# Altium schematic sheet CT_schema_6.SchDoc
size 269 x 267 mm
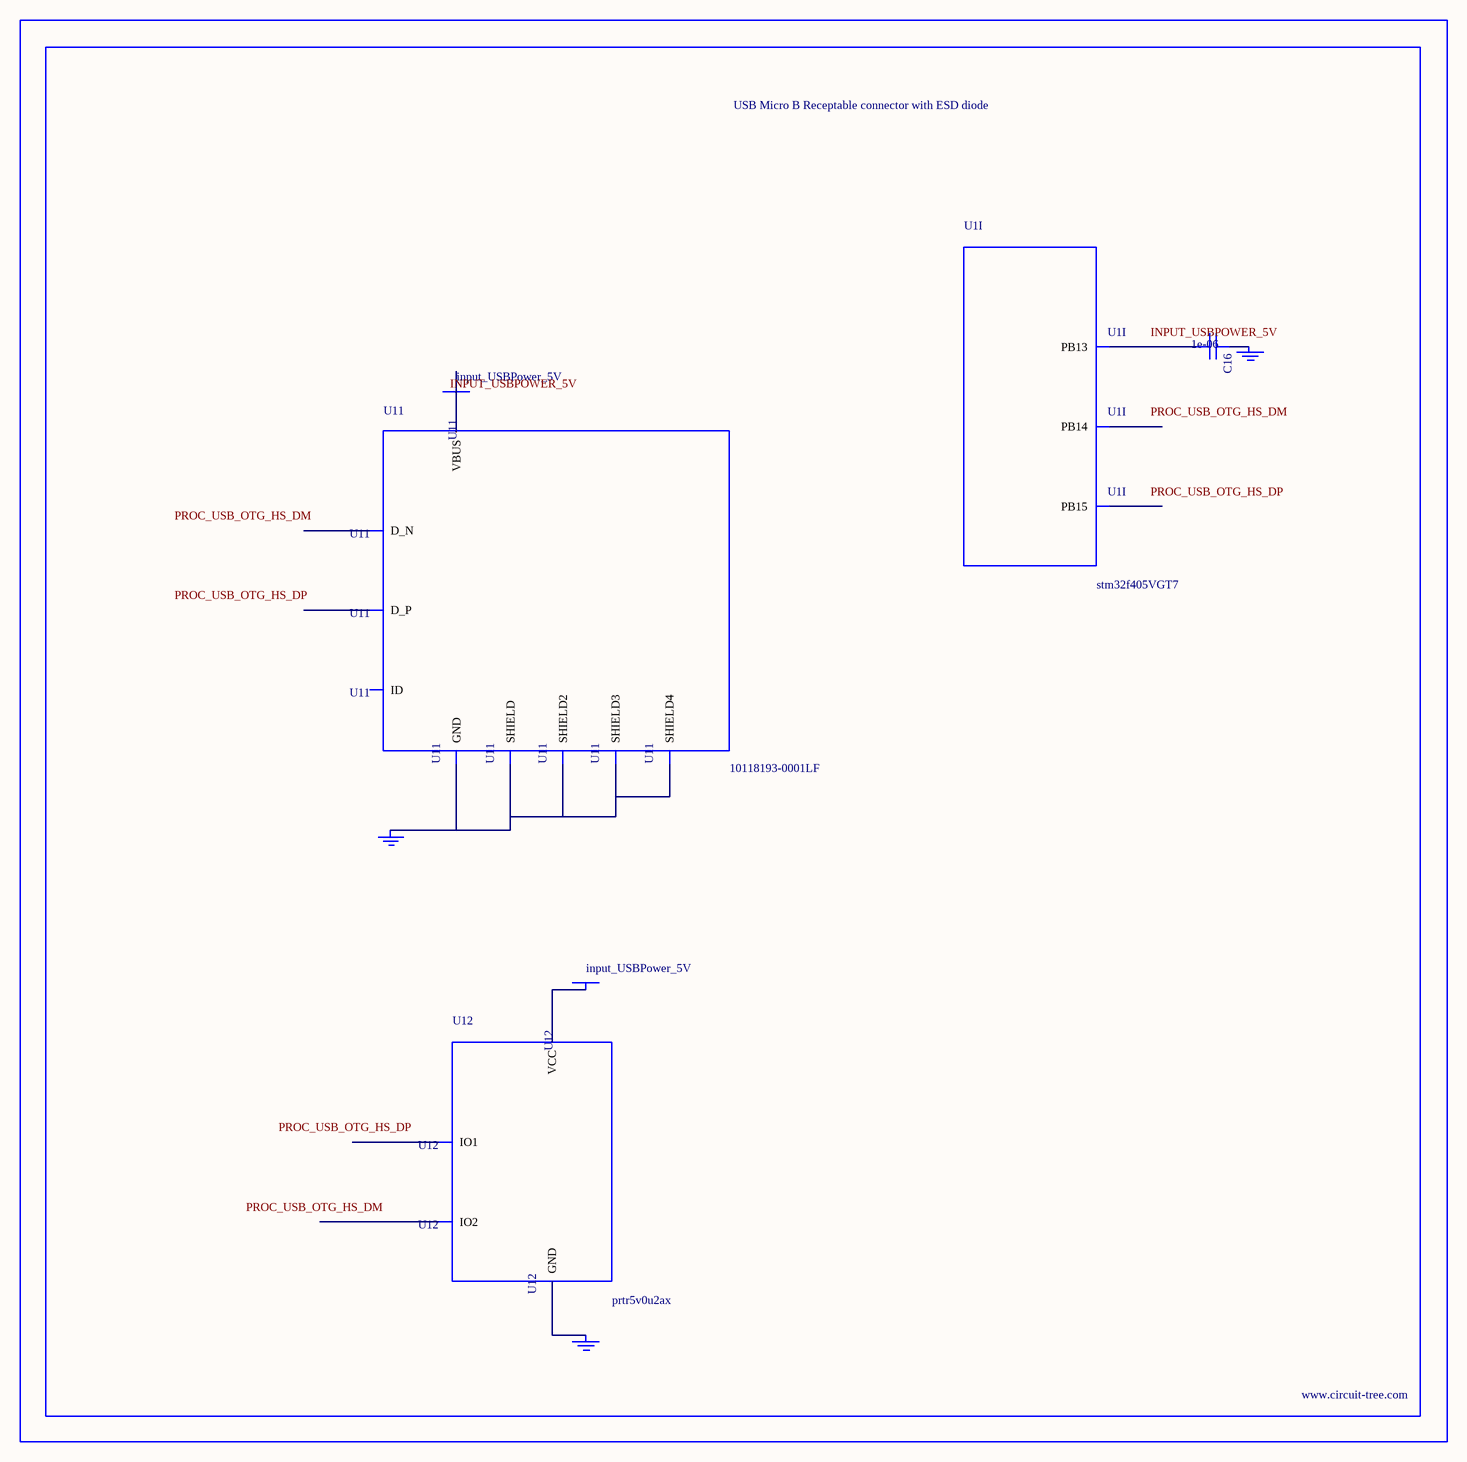
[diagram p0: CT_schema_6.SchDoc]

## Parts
BORDER5  (no value)
C16  1e-06  [C0603]
GND_INSTANCE_5_0  (no value)
GND_INSTANCE_5_1  (no value)
GND_INSTANCE_5_2  (no value)
POWER_INSTANCE_5_0  input_USBPower_5V
POWER_INSTANCE_5_1  input_USBPower_5V
U1  stm32f405VGT7  [LQFP100]  (part I of 10)
U11  10118193-0001LF  [FCI_10118193-0001LF]
U12  prtr5v0u2ax  [SOT143B]

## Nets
NetC16_1: C16.1 GND_INSTANCE_5_1.0(GND)
NetC16_2: C16.2 U1.52(PB13)
NetGND_INSTANCE_5_0_0: GND_INSTANCE_5_0.0(GND) U11.5(GND) U11.6(SHIELD) U11.7(SHIELD2) U11.8(SHIELD3) U11.9(SHIELD4)
NetGND_INSTANCE_5_2_0: GND_INSTANCE_5_2.0(GND) U12.1(GND)
NetPOWER_INSTANCE_5_0_0: POWER_INSTANCE_5_0.0(PWR) U11.1(VBUS)
NetPOWER_INSTANCE_5_1_0: POWER_INSTANCE_5_1.0(PWR) U12.4(VCC)

Not connected (* = marked no-connect by the designer): U1 53(PB14) 54(PB15); U11 2(D_N) 3(D_P) 4(ID); U12 2(IO1) 3(IO2)

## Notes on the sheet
- Labels drawn without touching a wire or pin: INPUT_USBPOWER_5V, PROC_USB_OTG_HS_DM, PROC_USB_OTG_HS_DP

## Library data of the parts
BORDER5 = BORDER_PAGE5
C16 = C0603C105K3RACTU
GND_INSTANCE_5_0-GND_INSTANCE_5_2 = GND
POWER_INSTANCE_5_0 POWER_INSTANCE_5_1 = PWR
